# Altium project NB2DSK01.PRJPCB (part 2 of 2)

## Sheet XC3S1500-4FG676C_PWRSETUP.SchDoc: XC3S1500-4FG676C POWER
size A4; Organization: Altium Limited.; Address1: Level 3, 12a Rodborough Rd; Address2: Frenchs Forest 2086; Address3: NSW; Address4: AUSTRALIA; DocumentNumber: 14; Revision: 6; SheetNumber: 14; SheetTotal: 64; PageSetup: Record=PageOptions|CenterHorizontal=True|CenterVertical=True|PrintScale=0.97|XCorrection=1.00|YCorrection=1.00|PrintKind=0|BorderSize=5000000|LeftOffset=0|BottomOffset=0|Orientation=2|PaperLength=1000|PaperWidth=1000|Scale=100|PaperSource=7|PrintQuality=-4|MediaType=1|DitherType=10|PaperKind=A4 (210 x 297 mm)|PrintScaleMode=1
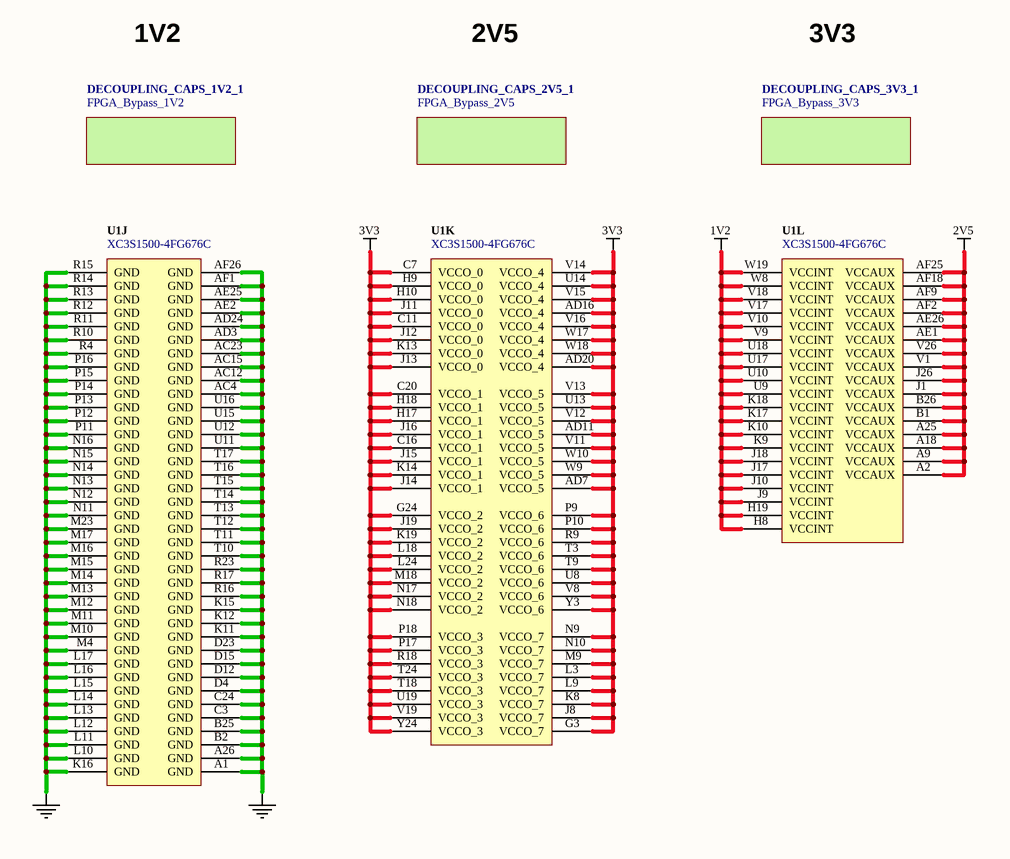
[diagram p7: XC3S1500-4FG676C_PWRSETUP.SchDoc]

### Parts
(Parts that share a designator on the sheet are numbered #1, #2 ... from top to bottom, then left to right.)
U1#1  XC3S1500-4FG676C  [BGA100P26X26-676]  (parts J,K,L of 12)

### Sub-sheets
DECOUPLING_CAPS_1V2_1 = FPGA_Bypass_1V2 (file not in this document): no entries
DECOUPLING_CAPS_2V5_1 = FPGA_Bypass_2V5 (file not in this document): no entries
DECOUPLING_CAPS_3V3_1 = FPGA_Bypass_3V3 (file not in this document): no entries

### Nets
1V2: U1#1.H8(VCCINT) U1#1.H19(VCCINT) U1#1.J9(VCCINT) U1#1.J10(VCCINT) U1#1.J17(VCCINT) U1#1.J18(VCCINT) U1#1.K9(VCCINT) U1#1.K10(VCCINT) U1#1.K17(VCCINT) U1#1.K18(VCCINT) U1#1.U9(VCCINT) U1#1.U10(VCCINT) U1#1.U17(VCCINT) U1#1.U18(VCCINT) U1#1.V9(VCCINT) U1#1.V10(VCCINT) U1#1.V17(VCCINT) U1#1.V18(VCCINT) U1#1.W8(VCCINT) U1#1.W19(VCCINT)
2V5: U1#1.A2(VCCAUX) U1#1.A9(VCCAUX) U1#1.A18(VCCAUX) U1#1.A25(VCCAUX) U1#1.AE1(VCCAUX) U1#1.AE26(VCCAUX) U1#1.AF2(VCCAUX) U1#1.AF9(VCCAUX) U1#1.AF18(VCCAUX) U1#1.AF25(VCCAUX) U1#1.B1(VCCAUX) U1#1.B26(VCCAUX) U1#1.J1(VCCAUX) U1#1.J26(VCCAUX) U1#1.V1(VCCAUX) U1#1.V26(VCCAUX)
3V3: U1#1.AD7(VCCO_5) U1#1.AD11(VCCO_5) U1#1.AD16(VCCO_4) U1#1.AD20(VCCO_4) U1#1.C7(VCCO_0) U1#1.C11(VCCO_0) U1#1.C16(VCCO_1) U1#1.C20(VCCO_1) U1#1.G3(VCCO_7) U1#1.G24(VCCO_2) U1#1.H9(VCCO_0) U1#1.H10(VCCO_0) U1#1.H17(VCCO_1) U1#1.H18(VCCO_1) U1#1.J8(VCCO_7) U1#1.J11(VCCO_0) U1#1.J12(VCCO_0) U1#1.J13(VCCO_0) U1#1.J14(VCCO_1) U1#1.J15(VCCO_1) U1#1.J16(VCCO_1) U1#1.J19(VCCO_2) U1#1.K8(VCCO_7) U1#1.K13(VCCO_0) U1#1.K14(VCCO_1) U1#1.K19(VCCO_2) U1#1.L3(VCCO_7) U1#1.L9(VCCO_7) U1#1.L18(VCCO_2) U1#1.L24(VCCO_2) U1#1.M9(VCCO_7) U1#1.M18(VCCO_2) U1#1.N9(VCCO_7) U1#1.N10(VCCO_7) U1#1.N17(VCCO_2) U1#1.N18(VCCO_2) U1#1.P9(VCCO_6) U1#1.P10(VCCO_6) U1#1.P17(VCCO_3) U1#1.P18(VCCO_3) U1#1.R9(VCCO_6) U1#1.R18(VCCO_3) U1#1.T3(VCCO_6) U1#1.T9(VCCO_6) U1#1.T18(VCCO_3) U1#1.T24(VCCO_3) U1#1.U8(VCCO_6) U1#1.U13(VCCO_5) U1#1.U14(VCCO_4) U1#1.U19(VCCO_3) U1#1.V8(VCCO_6) U1#1.V11(VCCO_5) U1#1.V12(VCCO_5) U1#1.V13(VCCO_5) U1#1.V14(VCCO_4) U1#1.V15(VCCO_4) U1#1.V16(VCCO_4) U1#1.V19(VCCO_3) U1#1.W9(VCCO_5) U1#1.W10(VCCO_5) U1#1.W17(VCCO_4) U1#1.W18(VCCO_4) U1#1.Y3(VCCO_6) U1#1.Y24(VCCO_3)
GND: U1#1.A1(GND) U1#1.A26(GND) U1#1.AC4(GND) U1#1.AC12(GND) U1#1.AC15(GND) U1#1.AC23(GND) U1#1.AD3(GND) U1#1.AD24(GND) U1#1.AE2(GND) U1#1.AE25(GND) U1#1.AF1(GND) U1#1.AF26(GND) U1#1.B2(GND) U1#1.B25(GND) U1#1.C3(GND) U1#1.C24(GND) U1#1.D4(GND) U1#1.D12(GND) U1#1.D15(GND) U1#1.D23(GND) U1#1.K11(GND) U1#1.K12(GND) U1#1.K15(GND) U1#1.K16(GND) U1#1.L10(GND) U1#1.L11(GND) U1#1.L12(GND) U1#1.L13(GND) U1#1.L14(GND) U1#1.L15(GND) U1#1.L16(GND) U1#1.L17(GND) U1#1.M4(GND) U1#1.M10(GND) U1#1.M11(GND) U1#1.M12(GND) U1#1.M13(GND) U1#1.M14(GND) U1#1.M15(GND) U1#1.M16(GND) U1#1.M17(GND) U1#1.M23(GND) U1#1.N11(GND) U1#1.N12(GND) U1#1.N13(GND) U1#1.N14(GND) U1#1.N15(GND) U1#1.N16(GND) U1#1.P11(GND) U1#1.P12(GND) U1#1.P13(GND) U1#1.P14(GND) U1#1.P15(GND) U1#1.P16(GND) U1#1.R4(GND) U1#1.R10(GND) U1#1.R11(GND) U1#1.R12(GND) U1#1.R13(GND) U1#1.R14(GND) U1#1.R15(GND) U1#1.R16(GND) U1#1.R17(GND) U1#1.R23(GND) U1#1.T10(GND) U1#1.T11(GND) U1#1.T12(GND) U1#1.T13(GND) U1#1.T14(GND) U1#1.T15(GND) U1#1.T16(GND) U1#1.T17(GND) U1#1.U11(GND) U1#1.U12(GND) U1#1.U15(GND) U1#1.U16(GND)

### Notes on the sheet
- 1V2
- 2V5
- 3V3

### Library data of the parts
U1#1 = D-241-0001: FPGA, Xilinx Spartan3-1500 FG676 Speed=4; Supply Voltage: mV

## Sheet CURRENT_SENSE.SchDoc: DB/PB Current Sense
size A3
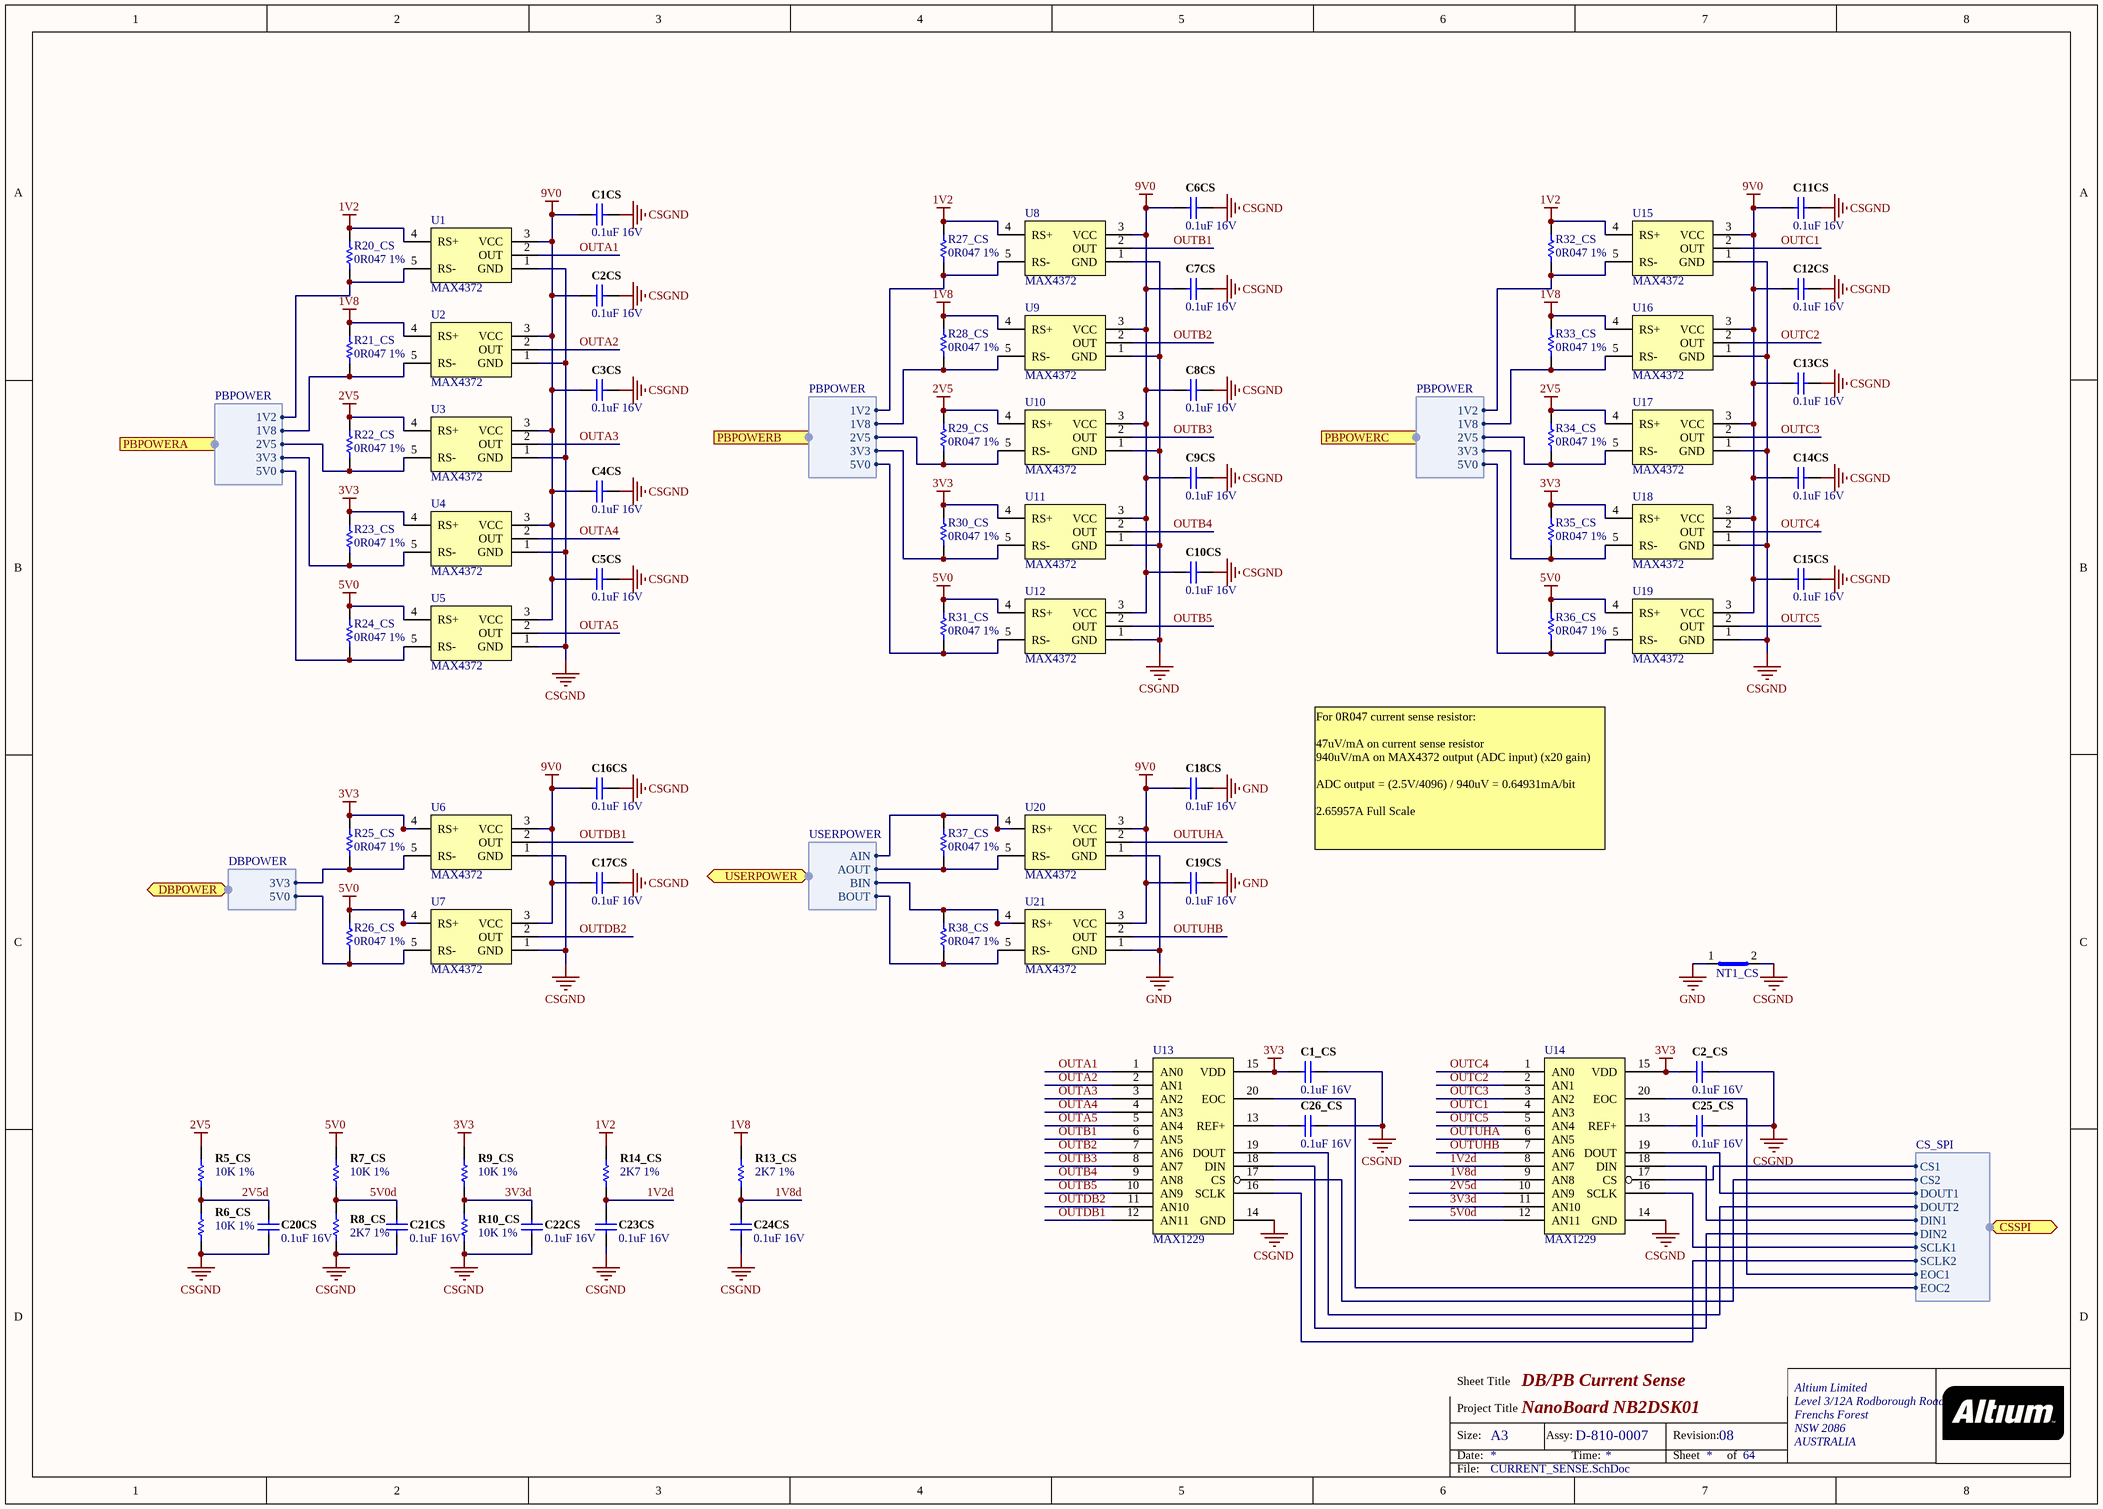
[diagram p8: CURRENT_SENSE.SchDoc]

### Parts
(Parts that share a designator on the sheet are numbered #1, #2 ... from top to bottom, then left to right.)
C1_CS  0.1uF 16V  [CAPC1005-STAR]
C1CS  0.1uF 16V  [CAPC1005-STAR]
C2_CS  0.1uF 16V  [CAPC1005-STAR]
C2CS  0.1uF 16V  [CAPC1005-STAR]
C3CS  0.1uF 16V  [CAPC1005-STAR]
C4CS  0.1uF 16V  [CAPC1005-STAR]
C5CS  0.1uF 16V  [CAPC1005-STAR]
C6CS  0.1uF 16V  [CAPC1005-STAR]
C7CS  0.1uF 16V  [CAPC1005-STAR]
C8CS  0.1uF 16V  [CAPC1005-STAR]
C9CS  0.1uF 16V  [CAPC1005-STAR]
C10CS  0.1uF 16V  [CAPC1005-STAR]
C11CS  0.1uF 16V  [CAPC1005-STAR]
C12CS  0.1uF 16V  [CAPC1005-STAR]
C13CS  0.1uF 16V  [CAPC1005-STAR]
C14CS  0.1uF 16V  [CAPC1005-STAR]
C15CS  0.1uF 16V  [CAPC1005-STAR]
C16CS  0.1uF 16V  [CAPC1005-STAR]
C17CS  0.1uF 16V  [CAPC1005-STAR]
C18CS  0.1uF 16V  [CAPC1005-STAR]
C19CS  0.1uF 16V  [CAPC1005-STAR]
C20CS  0.1uF 16V  [CAPC1005-STAR]
C21CS  0.1uF 16V  [CAPC1005-STAR]
C22CS  0.1uF 16V  [CAPC1005-STAR]
C23CS  0.1uF 16V  [CAPC1005-STAR]
C24CS  0.1uF 16V  [CAPC1005-STAR]
C25_CS  0.1uF 16V  [CAPC1005-STAR]
C26_CS  0.1uF 16V  [CAPC1005-STAR]
NT1_CS  Net Tie SMT2  [NETTIE-SMT2-8X8]  (value not drawn)  (net tie, no BOM)
R5_CS  10K 1%  [RESC1005-STAR]
R6_CS  10K 1%  [RESC1005-STAR]
R7_CS  10K 1%  [RESC1005-STAR]
R8_CS  2K7 1%  [RESC1005-STAR]
R9_CS  10K 1%  [RESC1005-STAR]
R10_CS  10K 1%  [RESC1005-STAR]
R13_CS  2K7 1%  [RESC1005-STAR]
R14_CS  2K7 1%  [RESC1005-STAR]
R20_CS  0R047 1%  [RESC3216]
R21_CS  0R047 1%  [RESC3216]
R22_CS  0R047 1%  [RESC3216]
R23_CS  0R047 1%  [RESC3216]
R24_CS  0R047 1%  [RESC3216]
R25_CS  0R047 1%  [RESC3216]
R26_CS  0R047 1%  [RESC3216]
R27_CS  0R047 1%  [RESC3216]
R28_CS  0R047 1%  [RESC3216]
R29_CS  0R047 1%  [RESC3216]
R30_CS  0R047 1%  [RESC3216]
R31_CS  0R047 1%  [RESC3216]
R32_CS  0R047 1%  [RESC3216]
R33_CS  0R047 1%  [RESC3216]
R34_CS  0R047 1%  [RESC3216]
R35_CS  0R047 1%  [RESC3216]
R36_CS  0R047 1%  [RESC3216]
R37_CS  0R047 1%  [RESC3216]
R38_CS  0R047 1%  [RESC3216]
U1#2  MAX4372  [SOT-23-5]
U2  MAX4372  [SOT-23-5]
U3  MAX4372  [SOT-23-5]
U4  MAX4372  [SOT-23-5]
U5  MAX4372  [SOT-23-5]
U6  MAX4372  [SOT-23-5]
U7  MAX4372  [SOT-23-5]
U8  MAX4372  [SOT-23-5]
U9  MAX4372  [SOT-23-5]
U10  MAX4372  [SOT-23-5]
U11  MAX4372  [SOT-23-5]
U12  MAX4372  [SOT-23-5]
U13  MAX1229  [QSOP65P600-20]
U14  MAX1229  [QSOP65P600-20]
U15  MAX4372  [SOT-23-5]
U16  MAX4372  [SOT-23-5]
U17  MAX4372  [SOT-23-5]
U18  MAX4372  [SOT-23-5]
U19  MAX4372  [SOT-23-5]
U20  MAX4372  [SOT-23-5]
U21  MAX4372  [SOT-23-5]

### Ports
CSSPI (harness CS_SPI), DBPOWER (harness DBPOWER), PBPOWERA (harness PBPOWER), PBPOWERB (harness PBPOWER), PBPOWERC (harness PBPOWER), USERPOWER (harness USERPOWER)

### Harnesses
PBPOWER: 1V2, 1V8, 2V5, 3V3, 5V0
DBPOWER: 3V3, 5V0
USERPOWER: AIN, BIN, AOUT, BOUT
CS_SPI: CS2, DOUT1, DOUT2, DIN1, CS1, DIN2, SCLK1, EOC1, SCLK2, EOC2

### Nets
1V2: R14_CS.2 R20_CS.1 R27_CS.1 R32_CS.1 U1#2.4(RS+) U8.4(RS+) U15.4(RS+)
1V8: R13_CS.2 R21_CS.1 R28_CS.1 R33_CS.1 U2.4(RS+) U9.4(RS+) U16.4(RS+)
2V5: R5_CS.2 R22_CS.1 R29_CS.1 R34_CS.1 U3.4(RS+) U10.4(RS+) U17.4(RS+)
3V3: C1_CS.1 C2_CS.1 R9_CS.2 R23_CS.1 R25_CS.1 R30_CS.1 R35_CS.1 U4.4(RS+) U6.4(RS+) U11.4(RS+) U13.15(VDD) U14.15(VDD) U18.4(RS+)
5V0: R7_CS.2 R24_CS.1 R26_CS.1 R31_CS.1 R36_CS.1 U5.4(RS+) U7.4(RS+) U12.4(RS+) U19.4(RS+)
9V0: C1CS.1 C2CS.1 C3CS.1 C4CS.1 C5CS.1 C6CS.1 C7CS.1 C8CS.1 C9CS.1 C10CS.1 C11CS.1 C12CS.1 C13CS.1 C14CS.1 C15CS.1 C16CS.1 C17CS.1 C18CS.1 C19CS.1 U1#2.3(VCC) U2.3(VCC) U3.3(VCC) U4.3(VCC) U5.3(VCC) U6.3(VCC) U7.3(VCC) U8.3(VCC) U9.3(VCC) U10.3(VCC) U11.3(VCC) U12.3(VCC) U15.3(VCC) U16.3(VCC) U17.3(VCC) U18.3(VCC) U19.3(VCC) U20.3(VCC) U21.3(VCC)
CSGND: C1_CS.2 C1CS.2 C2_CS.2 C2CS.2 C3CS.2 C4CS.2 C5CS.2 C6CS.2 C7CS.2 C8CS.2 C9CS.2 C10CS.2 C11CS.2 C12CS.2 C13CS.2 C14CS.2 C15CS.2 C16CS.2 C17CS.2 C20CS.1 C21CS.1 C22CS.1 C23CS.1 C24CS.1 C25_CS.2 C26_CS.2 NT1_CS.2(Net2) R6_CS.1 R8_CS.1 R10_CS.1 U1#2.1(GND) U2.1(GND) U3.1(GND) U4.1(GND) U5.1(GND) U6.1(GND) U7.1(GND) U8.1(GND) U9.1(GND) U10.1(GND) U11.1(GND) U12.1(GND) U13.14(GND) U14.14(GND) U15.1(GND) U16.1(GND) U17.1(GND) U18.1(GND) U19.1(GND)
GND: C18CS.2 C19CS.2 NT1_CS.1(Net1) U20.1(GND) U21.1(GND)
1V2d: C23CS.2 R14_CS.1 U14.8(AN7)
1V8d: C24CS.2 R13_CS.1 U14.9(AN8)
2V5d: C20CS.2 R5_CS.1 R6_CS.2 U14.10(AN9)
3V3d: C22CS.2 R9_CS.1 R10_CS.2 U14.11(AN10)
5V0d: C21CS.2 R7_CS.1 R8_CS.2 U14.12(AN11)
CSSPI_CS1: U14.17(CS) ; port CSSPI.CS1
CSSPI_CS2: U13.17(CS) ; port CSSPI.CS2
CSSPI_DIN: U14.18(DIN) ; port CSSPI.DIN1
CSSPI_DIN2: U13.18(DIN) ; port CSSPI.DIN2
CSSPI_DOUT: U14.19(DOUT) ; port CSSPI.DOUT1
CSSPI_DOUT2: U13.19(DOUT) ; port CSSPI.DOUT2
CSSPI_EOC1: U14.20(EOC) ; port CSSPI.EOC1
CSSPI_EOC2: U13.20(EOC) ; port CSSPI.EOC2
CSSPI_SCLK: U14.16(SCLK) ; port CSSPI.SCLK1
CSSPI_SCLK2: U13.16(SCLK) ; port CSSPI.SCLK2
OUTA1: U1#2.2(OUT) U13.1(AN0)
OUTA2: U2.2(OUT) U13.2(AN1)
OUTA3: U3.2(OUT) U13.3(AN2)
OUTA4: U4.2(OUT) U13.4(AN3)
OUTA5: U5.2(OUT) U13.5(AN4)
OUTB1: U8.2(OUT) U13.6(AN5)
OUTB2: U9.2(OUT) U13.7(AN6)
OUTB3: U10.2(OUT) U13.8(AN7)
OUTB4: U11.2(OUT) U13.9(AN8)
OUTB5: U12.2(OUT) U13.10(AN9)
OUTC1: U14.4(AN3) U15.2(OUT)
OUTC2: U14.2(AN1) U16.2(OUT)
OUTC3: U14.3(AN2) U17.2(OUT)
OUTC4: U14.1(AN0) U18.2(OUT)
OUTC5: U14.5(AN4) U19.2(OUT)
OUTDB1: U6.2(OUT) U13.12(AN11)
OUTDB2: U7.2(OUT) U13.11(AN10)
OUTUHA: U14.6(AN5) U20.2(OUT)
OUTUHB: U14.7(AN6) U21.2(OUT)
NetC25_CS_1: C25_CS.1 U14.13(REF+)
NetC26_CS_1: C26_CS.1 U13.13(REF+)
NetR20_CS_2: R20_CS.2 U1#2.5(RS-) ; port PBPOWERA.1V2
NetR21_CS_2: R21_CS.2 U2.5(RS-) ; port PBPOWERA.1V8
NetR22_CS_2: R22_CS.2 U3.5(RS-) ; port PBPOWERA.2V5
NetR23_CS_2: R23_CS.2 U4.5(RS-) ; port PBPOWERA.3V3
NetR24_CS_2: R24_CS.2 U5.5(RS-) ; port PBPOWERA.5V0
NetR25_CS_2: R25_CS.2 U6.5(RS-) ; port DBPOWER.3V3
NetR26_CS_2: R26_CS.2 U7.5(RS-) ; port DBPOWER.5V0
NetR27_CS_2: R27_CS.2 U8.5(RS-) ; port PBPOWERB.1V2
NetR28_CS_2: R28_CS.2 U9.5(RS-) ; port PBPOWERB.1V8
NetR29_CS_2: R29_CS.2 U10.5(RS-) ; port PBPOWERB.2V5
NetR30_CS_2: R30_CS.2 U11.5(RS-) ; port PBPOWERB.3V3
NetR31_CS_2: R31_CS.2 U12.5(RS-) ; port PBPOWERB.5V0
NetR32_CS_2: R32_CS.2 U15.5(RS-) ; port PBPOWERC.1V2
NetR33_CS_2: R33_CS.2 U16.5(RS-) ; port PBPOWERC.1V8
NetR34_CS_2: R34_CS.2 U17.5(RS-) ; port PBPOWERC.2V5
NetR35_CS_2: R35_CS.2 U18.5(RS-) ; port PBPOWERC.3V3
NetR36_CS_2: R36_CS.2 U19.5(RS-) ; port PBPOWERC.5V0
NetR37_CS_1: R37_CS.1 U20.4(RS+) ; port USERPOWER.AIN
NetR37_CS_2: R37_CS.2 U20.5(RS-) ; port USERPOWER.AOUT
NetR38_CS_1: R38_CS.1 U21.4(RS+) ; port USERPOWER.BIN
NetR38_CS_2: R38_CS.2 U21.5(RS-) ; port USERPOWER.BOUT

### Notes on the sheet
- For 0R047 current sense resistor:
  47uV/mA on current sense resistor
  940uV/mA on MAX4372 output (ADC input) (x20 gain)
  ADC output = (2.5V/4096) / 940uV = 0.64931mA/bit
  2.65957A Full Scale

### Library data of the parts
C1_CS C1CS C2_CS C2CS C3CS C4CS C5CS C6CS C7CS C8CS C9CS C10CS C11CS C12CS C13CS C14CS C15CS C16CS C17CS C18CS C19CS C20CS C21CS C22CS C23CS C24CS C25_CS C26_CS = D-101-0080: Capacitor, Ceramic, 0.1uF 10% 16V 0402 (1005) X7R; Polarity: Non-Polarized
NT1_CS = D-002-0002: Net-Tie, Surface Mount, 2 x 0.4mm x 0.2mm SMT Pads - For 0.2mm Track
R5_CS R6_CS R7_CS R9_CS R10_CS = D-100-0130: Resistor, 10K 1% 0402 (1005); Power Rating: 63 mW
R8_CS R13_CS R14_CS = D-100-0105: Resistor, 2K7 1% 0402 (1005); Power Rating: 63 mW; Resistance: 2.7 K
R20_CS R21_CS R22_CS R23_CS R24_CS R25_CS R26_CS R27_CS R28_CS R29_CS R30_CS R31_CS R32_CS R33_CS R34_CS R35_CS R36_CS R37_CS R38_CS = D-100-0007: Resistor, 0R047, LRC02P, SMD, 1206, Thick Film, Current Sense, 1%; Power Rating: mW; Resistance: 47 mR
U1#2 U2-U12 U15-U21 = D-204-0012: MAX4372 High Side Current Sense Amplifier; Max Input Voltage: mV; Max Output Current: mA
U13 U14 = D-220-0003: MAX1229, 12bit ADC, 12 channel, 3.3V, SPI; Bit Width: 12 Bits; Max Sample Frequency: Hz

## Sheet NB2_DB.SchDoc
size A3
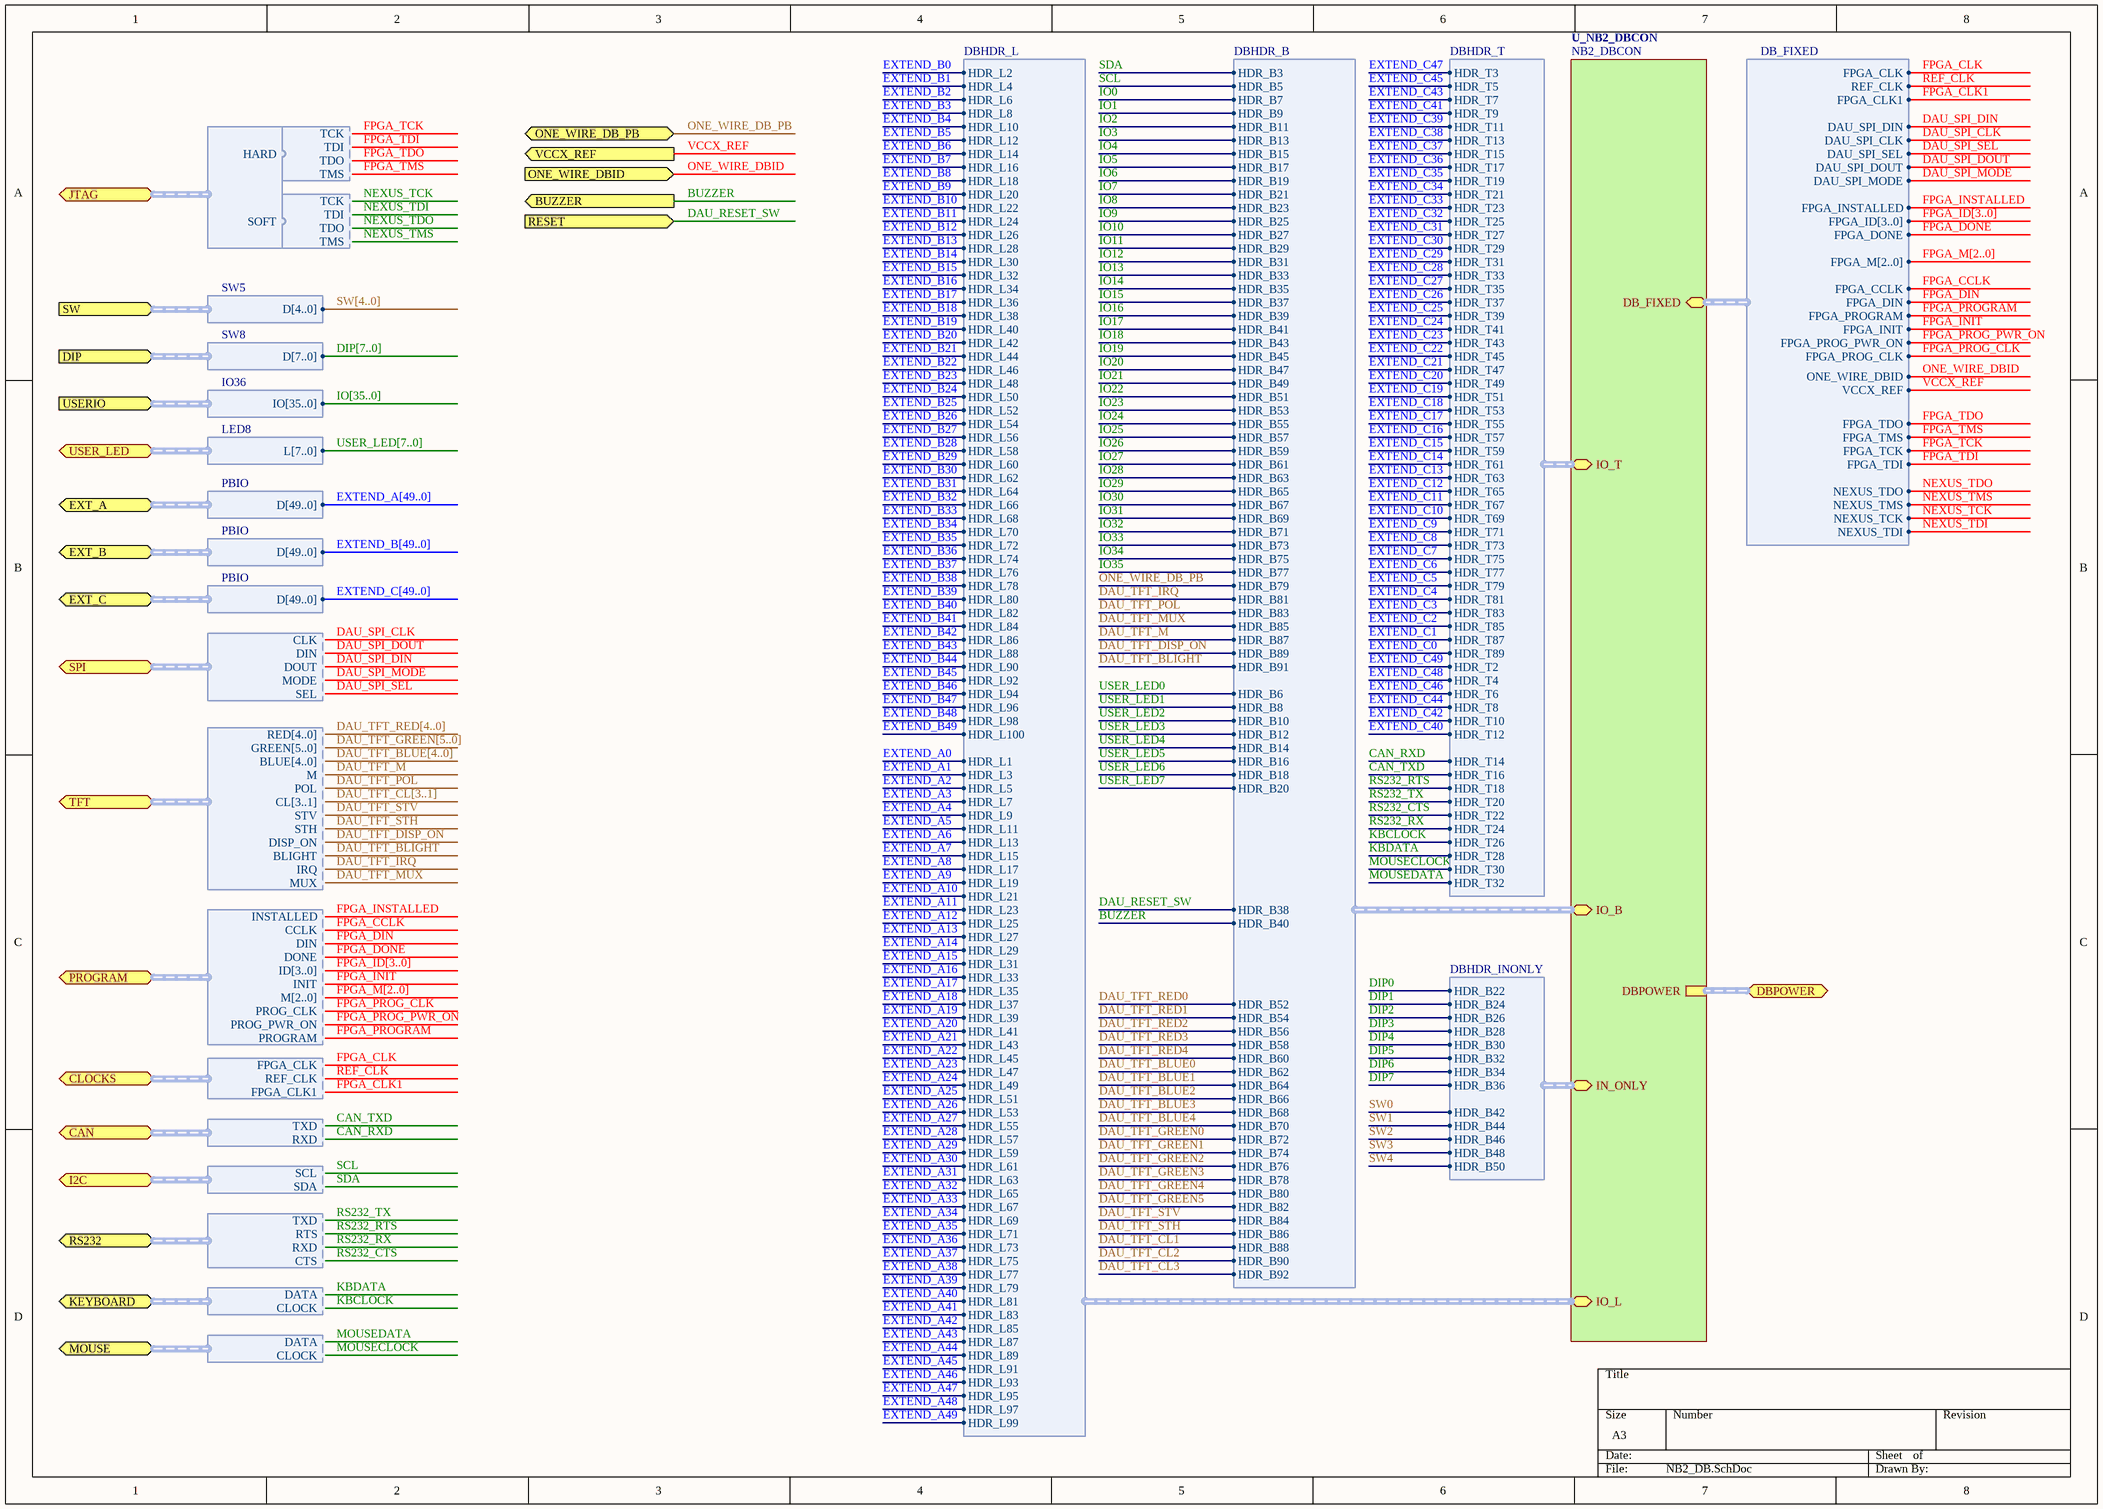
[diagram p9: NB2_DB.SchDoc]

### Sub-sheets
U_NB2_DBCON = NB2_DBCON (file not in this document): DBPOWER (harness DBPOWER), IO_B (harness DBHDR_B), DB_FIXED (harness DB_FIXED), IO_T (harness DBHDR_T), IN_ONLY (harness DBHDR_INONLY), IO_L (harness DBHDR_L)

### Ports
BUZZER (out), CAN (harness CAN_INT), CLOCKS (harness DAU_CLK), DBPOWER, DIP (harness SW8), EXT_A (harness PBIO), EXT_B (harness PBIO), EXT_C (harness PBIO), I2C (harness I2C), JTAG (harness HardSoft_JTAG), KEYBOARD (harness PS2), MOUSE (harness PS2), ONE_WIRE_DB_PB (bidir), ONE_WIRE_DBID (in), PROGRAM (harness DAU_CTRL), RESET (in), RS232 (harness RS232_INT), SPI (harness DAU_SPI), SW (harness SW5), TFT (harness DAU_TFT), USER_LED (harness LED8), USERIO (harness IO36), VCCX_REF (out)

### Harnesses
JTAG: TMS, TDO, TDI, TCK
HardSoft_JTAG: HARD, SOFT
LED8: L[7..0]
IO36: IO[35..0]
SW8: D[7..0]
SW5: D[4..0]
PBIO: D[49..0]
DAU_CLK: REF_CLK, FPGA_CLK, FPGA_CLK1
DAU_SPI: MODE, SEL, CLK, DIN, DOUT
DAU_CTRL: DIN, DONE, INSTALLED, ID[3..0], CCLK, PROGRAM, M[2..0], INIT, PROG_PWR_ON, PROG_CLK
DAU_TFT: RED[4..0], GREEN[5..0], BLUE[4..0], M, POL, CL[3..1], STV, STH, DISP_ON, BLIGHT, IRQ, MUX
PS2: DATA, CLOCK
CAN_INT: TXD, RXD
I2C: SCL, SDA
RS232_INT: RXD, TXD, RTS, CTS
DBHDR_B: HDR_B3, HDR_B5, HDR_B7, HDR_B9, HDR_B11, HDR_B13, HDR_B15, HDR_B17, HDR_B19, HDR_B21, HDR_B23, HDR_B25, HDR_B27, HDR_B29, HDR_B31, HDR_B33, HDR_B35, HDR_B37, HDR_B39, HDR_B41, HDR_B43, HDR_B45, HDR_B47, HDR_B49, HDR_B51, HDR_B53, HDR_B55, HDR_B57, HDR_B59, HDR_B61, HDR_B63, HDR_B65, HDR_B67, HDR_B69, HDR_B71, HDR_B73, HDR_B75, HDR_B77, HDR_B79, HDR_B81, HDR_B83, HDR_B85, HDR_B87, HDR_B89, HDR_B91, HDR_B6, HDR_B8, HDR_B10, HDR_B12, HDR_B14, HDR_B16, HDR_B18, HDR_B20, HDR_B38, HDR_B40, HDR_B52, HDR_B54, HDR_B56, HDR_B58, HDR_B60, HDR_B62, HDR_B64, HDR_B66, HDR_B68, HDR_B70, HDR_B72, HDR_B74, HDR_B76, HDR_B78, HDR_B80, HDR_B82, HDR_B84, HDR_B86, HDR_B88, HDR_B90, HDR_B92
DBHDR_T: HDR_T3, HDR_T5, HDR_T7, HDR_T9, HDR_T11, HDR_T13, HDR_T15, HDR_T17, HDR_T19, HDR_T21, HDR_T23, HDR_T25, HDR_T27, HDR_T29, HDR_T31, HDR_T33, HDR_T35, HDR_T37, HDR_T39, HDR_T41, HDR_T43, HDR_T45, HDR_T47, HDR_T49, HDR_T51, HDR_T53, HDR_T55, HDR_T57, HDR_T59, HDR_T61, HDR_T63, HDR_T65, HDR_T67, HDR_T69, HDR_T71, HDR_T73, HDR_T75, HDR_T77, HDR_T79, HDR_T81, HDR_T83, HDR_T85, HDR_T87, HDR_T89, HDR_T2, HDR_T4, HDR_T6, HDR_T8, HDR_T10, HDR_T12, HDR_T14, HDR_T16, HDR_T18, HDR_T20, HDR_T22, HDR_T24, HDR_T26, HDR_T28, HDR_T30, HDR_T32
DBHDR_L: HDR_L2, HDR_L4, HDR_L6, HDR_L8, HDR_L10, HDR_L12, HDR_L14, HDR_L16, HDR_L18, HDR_L20, HDR_L22, HDR_L24, HDR_L26, HDR_L28, HDR_L30, HDR_L32, HDR_L34, HDR_L36, HDR_L38, HDR_L40, HDR_L42, HDR_L44, HDR_L46, HDR_L48, HDR_L50, HDR_L52, HDR_L54, HDR_L56, HDR_L58, HDR_L60, HDR_L62, HDR_L64, HDR_L66, HDR_L68, HDR_L70, HDR_L72, HDR_L74, HDR_L76, HDR_L78, HDR_L80, HDR_L82, HDR_L84, HDR_L86, HDR_L88, HDR_L90, HDR_L92, HDR_L94, HDR_L96, HDR_L98, HDR_L100, HDR_L1, HDR_L3, HDR_L5, HDR_L7, HDR_L9, HDR_L11, HDR_L13, HDR_L15, HDR_L17, HDR_L19, HDR_L21, HDR_L23, HDR_L25, HDR_L27, HDR_L29, HDR_L31, HDR_L33, HDR_L35, HDR_L37, HDR_L39, HDR_L41, HDR_L43, HDR_L45, HDR_L47, HDR_L49, HDR_L51, HDR_L53, HDR_L55, HDR_L57, HDR_L59, HDR_L61, HDR_L63, HDR_L65, HDR_L67, HDR_L69, HDR_L71, HDR_L73, HDR_L75, HDR_L77, HDR_L79, HDR_L81, HDR_L83, HDR_L85, HDR_L87, HDR_L89, HDR_L91, HDR_L93, HDR_L95, HDR_L97, HDR_L99
DBHDR_INONLY: HDR_B22, HDR_B24, HDR_B26, HDR_B28, HDR_B30, HDR_B32, HDR_B34, HDR_B36, HDR_B42, HDR_B44, HDR_B46, HDR_B48, HDR_B50
DB_FIXED: DAU_SPI_CLK, DAU_SPI_DIN, DAU_SPI_DOUT, NEXUS_TMS, NEXUS_TDI, NEXUS_TDO, NEXUS_TCK, ONE_WIRE_DBID, FPGA_INSTALLED, FPGA_PROG_CLK, DAU_SPI_SEL, DAU_SPI_MODE, FPGA_PROG_PWR_ON, FPGA_DONE, FPGA_CCLK, FPGA_PROGRAM, FPGA_DIN, FPGA_INIT, FPGA_TDO, FPGA_TDI, FPGA_TCK, FPGA_TMS, FPGA_CLK1, FPGA_ID[3..0], FPGA_M[2..0], VCCX_REF, FPGA_CLK, REF_CLK

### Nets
BUZZER: port BUZZER, sheet U_NB2_DBCON/IO_B.HDR_B40
CAN_RXD: port CAN.RXD, sheet U_NB2_DBCON/IO_T.HDR_T14  [project net CAN.RXD]
CAN_TXD: port CAN.TXD, sheet U_NB2_DBCON/IO_T.HDR_T16  [project net CAN.TXD]
DAU_RESET_SW: port RESET, sheet U_NB2_DBCON/IO_B.HDR_B38
DAU_SPI_CLK: port SPI.CLK, sheet U_NB2_DBCON/DB_FIXED.DAU_SPI_CLK  [project net DAU_SPI.CLK]
DAU_SPI_DIN: port SPI.DOUT, sheet U_NB2_DBCON/DB_FIXED.DAU_SPI_DIN  [project net DAU_SPI.DOUT]
DAU_SPI_DOUT: port SPI.DIN, sheet U_NB2_DBCON/DB_FIXED.DAU_SPI_DOUT  [project net DAU_SPI.DIN]
DAU_SPI_MODE: port SPI.MODE, sheet U_NB2_DBCON/DB_FIXED.DAU_SPI_MODE  [project net DAU_SPI.MODE]
DAU_SPI_SEL: port SPI.SEL, sheet U_NB2_DBCON/DB_FIXED.DAU_SPI_SEL  [project net DAU_SPI.SEL]
DAU_TFT_BLIGHT: port TFT.BLIGHT, sheet U_NB2_DBCON/IO_B.HDR_B91  [project net DAU_TFT.BLIGHT]
DAU_TFT_DISP_ON: port TFT.DISP_ON, sheet U_NB2_DBCON/IO_B.HDR_B89  [project net DAU_TFT.DISP_ON]
DAU_TFT_IRQ: port TFT.IRQ, sheet U_NB2_DBCON/IO_B.HDR_B81  [project net DAU_TFT.IRQ]
DAU_TFT_M: port TFT.M, sheet U_NB2_DBCON/IO_B.HDR_B87  [project net DAU_TFT.M]
DAU_TFT_MUX: port TFT.MUX, sheet U_NB2_DBCON/IO_B.HDR_B85  [project net DAU_TFT.MUX]
DAU_TFT_POL: port TFT.POL, sheet U_NB2_DBCON/IO_B.HDR_B83  [project net DAU_TFT.POL]
DAU_TFT_STH: port TFT.STH, sheet U_NB2_DBCON/IO_B.HDR_B86  [project net DAU_TFT.STH]
DAU_TFT_STV: port TFT.STV, sheet U_NB2_DBCON/IO_B.HDR_B84  [project net DAU_TFT.STV]
FPGA_CCLK: port PROGRAM.CCLK, sheet U_NB2_DBCON/DB_FIXED.FPGA_CCLK  [project net DAU_PROG.CCLK]
FPGA_CLK: port CLOCKS.FPGA_CLK, sheet U_NB2_DBCON/DB_FIXED.FPGA_CLK  [project net CLKPLL.CLK_PROG]
FPGA_CLK1: port CLOCKS.FPGA_CLK1, sheet U_NB2_DBCON/DB_FIXED.FPGA_CLK1  [project net DAU_CLK.FPGA_CLK1]
FPGA_DIN: port PROGRAM.DIN, sheet U_NB2_DBCON/DB_FIXED.FPGA_DIN  [project net DAU_PROG.DIN]
FPGA_DONE: port PROGRAM.DONE, sheet U_NB2_DBCON/DB_FIXED.FPGA_DONE  [project net DAU_PROG.DONE]
FPGA_INIT: port PROGRAM.INIT, sheet U_NB2_DBCON/DB_FIXED.FPGA_INIT  [project net DAU_PROG.INIT]
FPGA_INSTALLED: port PROGRAM.INSTALLED, sheet U_NB2_DBCON/DB_FIXED.FPGA_INSTALLED  [project net DAU_PROG.INSTALLED]
FPGA_PROG_CLK: port PROGRAM.PROG_CLK, sheet U_NB2_DBCON/DB_FIXED.FPGA_PROG_CLK  [project net DAU_PROG.PROG_CLK]
FPGA_PROG_PWR_ON: port PROGRAM.PROG_PWR_ON, sheet U_NB2_DBCON/DB_FIXED.FPGA_PROG_PWR_ON  [project net DAU_PROG.PROG_PWR_ON]
FPGA_PROGRAM: port PROGRAM.PROGRAM, sheet U_NB2_DBCON/DB_FIXED.FPGA_PROGRAM  [project net DAU_PROG.PROGRAM]
FPGA_TCK: harness JTAG.TCK, sheet U_NB2_DBCON/DB_FIXED.FPGA_TCK
FPGA_TDI: harness JTAG.TDI, sheet U_NB2_DBCON/DB_FIXED.FPGA_TDI
FPGA_TDO: harness JTAG.TDO, sheet U_NB2_DBCON/DB_FIXED.FPGA_TDO
FPGA_TMS: harness JTAG.TMS, sheet U_NB2_DBCON/DB_FIXED.FPGA_TMS
KBCLOCK: port KEYBOARD.CLOCK, sheet U_NB2_DBCON/IO_T.HDR_T26  [project net KEYBOARD.CLOCK]
KBDATA: port KEYBOARD.DATA, sheet U_NB2_DBCON/IO_T.HDR_T28  [project net KEYBOARD.DATA]
MOUSECLOCK: port MOUSE.CLOCK, sheet U_NB2_DBCON/IO_T.HDR_T30  [project net MOUSE.CLOCK]
MOUSEDATA: port MOUSE.DATA, sheet U_NB2_DBCON/IO_T.HDR_T32  [project net MOUSE.DATA]
NEXUS_TCK: harness JTAG.TCK, sheet U_NB2_DBCON/DB_FIXED.NEXUS_TCK
NEXUS_TDI: harness JTAG.TDI, sheet U_NB2_DBCON/DB_FIXED.NEXUS_TDI
NEXUS_TDO: harness JTAG.TDO, sheet U_NB2_DBCON/DB_FIXED.NEXUS_TDO
NEXUS_TMS: harness JTAG.TMS, sheet U_NB2_DBCON/DB_FIXED.NEXUS_TMS
ONE_WIRE_DB_PB: port ONE_WIRE_DB_PB, sheet U_NB2_DBCON/IO_B.HDR_B79  [project net 1W_DBPB]
ONE_WIRE_DBID: port ONE_WIRE_DBID, sheet U_NB2_DBCON/DB_FIXED.ONE_WIRE_DBID  [project net 1W_DBID]
REF_CLK: port CLOCKS.REF_CLK, sheet U_NB2_DBCON/DB_FIXED.REF_CLK  [project net CLKPLL.CLK_FIXED]
RS232_CTS: port RS232.CTS, sheet U_NB2_DBCON/IO_T.HDR_T22  [project net RS232.CTS]
RS232_RTS: port RS232.RTS, sheet U_NB2_DBCON/IO_T.HDR_T18  [project net RS232.RTS]
RS232_RX: port RS232.RXD, sheet U_NB2_DBCON/IO_T.HDR_T24  [project net RS232.RXD]
RS232_TX: port RS232.TXD, sheet U_NB2_DBCON/IO_T.HDR_T20  [project net RS232.TXD]
SCL: port I2C.SCL, sheet U_NB2_DBCON/IO_B.HDR_B5  [project net I2C.SCL]
SDA: port I2C.SDA, sheet U_NB2_DBCON/IO_B.HDR_B3  [project net I2C.SDA]
VCCX_REF: port VCCX_REF, sheet U_NB2_DBCON/DB_FIXED.VCCX_REF

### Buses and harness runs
bus DAU_TFT_BLUE[4..0]
bus DAU_TFT_CL[3..1]
bus DAU_TFT_GREEN[5..0]
bus DAU_TFT_RED[4..0]
bus DIP[7..0]
bus EXTEND_A[49..0]
bus EXTEND_B[49..0]
bus EXTEND_C[49..0]
bus FPGA_ID[3..0]
bus FPGA_M[2..0]
bus IO[35..0]
bus SW[4..0]
bus USER_LED[7..0]
harness port DBPOWER = sheet U_NB2_DBCON/DBPOWER

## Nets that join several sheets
1V2: XC3S1500-4FG676C_PWRSETUP (20 pins), CURRENT_SENSE (7 pins)
2V5: FPGA_PRGSETUP (R1.1 R4.1 R5_S3.1), XC3S1500-4FG676C_PWRSETUP (16 pins), CURRENT_SENSE (7 pins)
3V3: NB2_PSU (C23_CM.1 C24_CM.1), FPGA_PRGSETUP (R7_S3.1), XC3S1500-4FG676C_PWRSETUP (64 pins), CURRENT_SENSE (13 pins)
5V0: NB2_PSU (C1.1 C2.1 C3.1 C4.1), PWJACK+SWITCH (J1OUT.1 SW8.1 SW8.2 TP2#1.1), CURRENT_SENSE (9 pins)
GND: NB2_PSU (16 pins), PWJACK+SWITCH (6 pins), FPGA_PRGSETUP (U1#1.AC3 U1#1.AE3 U1#1.AF3 U1#1.C2), XC3S1500-4FG676C_PWRSETUP (76 pins), CURRENT_SENSE (5 pins)
5VUSW: NB2_PSU (D1.2), PWJACK+SWITCH (F1.2 SW8.3)
CSSPI_CS1: Host_FPGA (U1#1.C12), CURRENT_SENSE (U14.17)
CSSPI_CS2: Host_FPGA (U1#1.AC7), CURRENT_SENSE (U13.17)
CSSPI_DIN: Host_FPGA (U1#1.U4), CURRENT_SENSE (U14.18)
CSSPI_DIN2: Host_FPGA (U1#1.AD15), CURRENT_SENSE (U13.18)
CSSPI_DOUT: Host_FPGA (U1#1.W5), CURRENT_SENSE (U14.19)
CSSPI_DOUT2: Host_FPGA (U1#1.AD18), CURRENT_SENSE (U13.19)
CSSPI_EOC1: Host_FPGA (U1#1.D11), CURRENT_SENSE (U14.20)
CSSPI_EOC2: Host_FPGA (U1#1.AC8), CURRENT_SENSE (U13.20)
CSSPI_SCLK: Host_FPGA (U1#1.T4), CURRENT_SENSE (U14.16)
CSSPI_SCLK2: Host_FPGA (U1#1.AB13), CURRENT_SENSE (U13.16)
